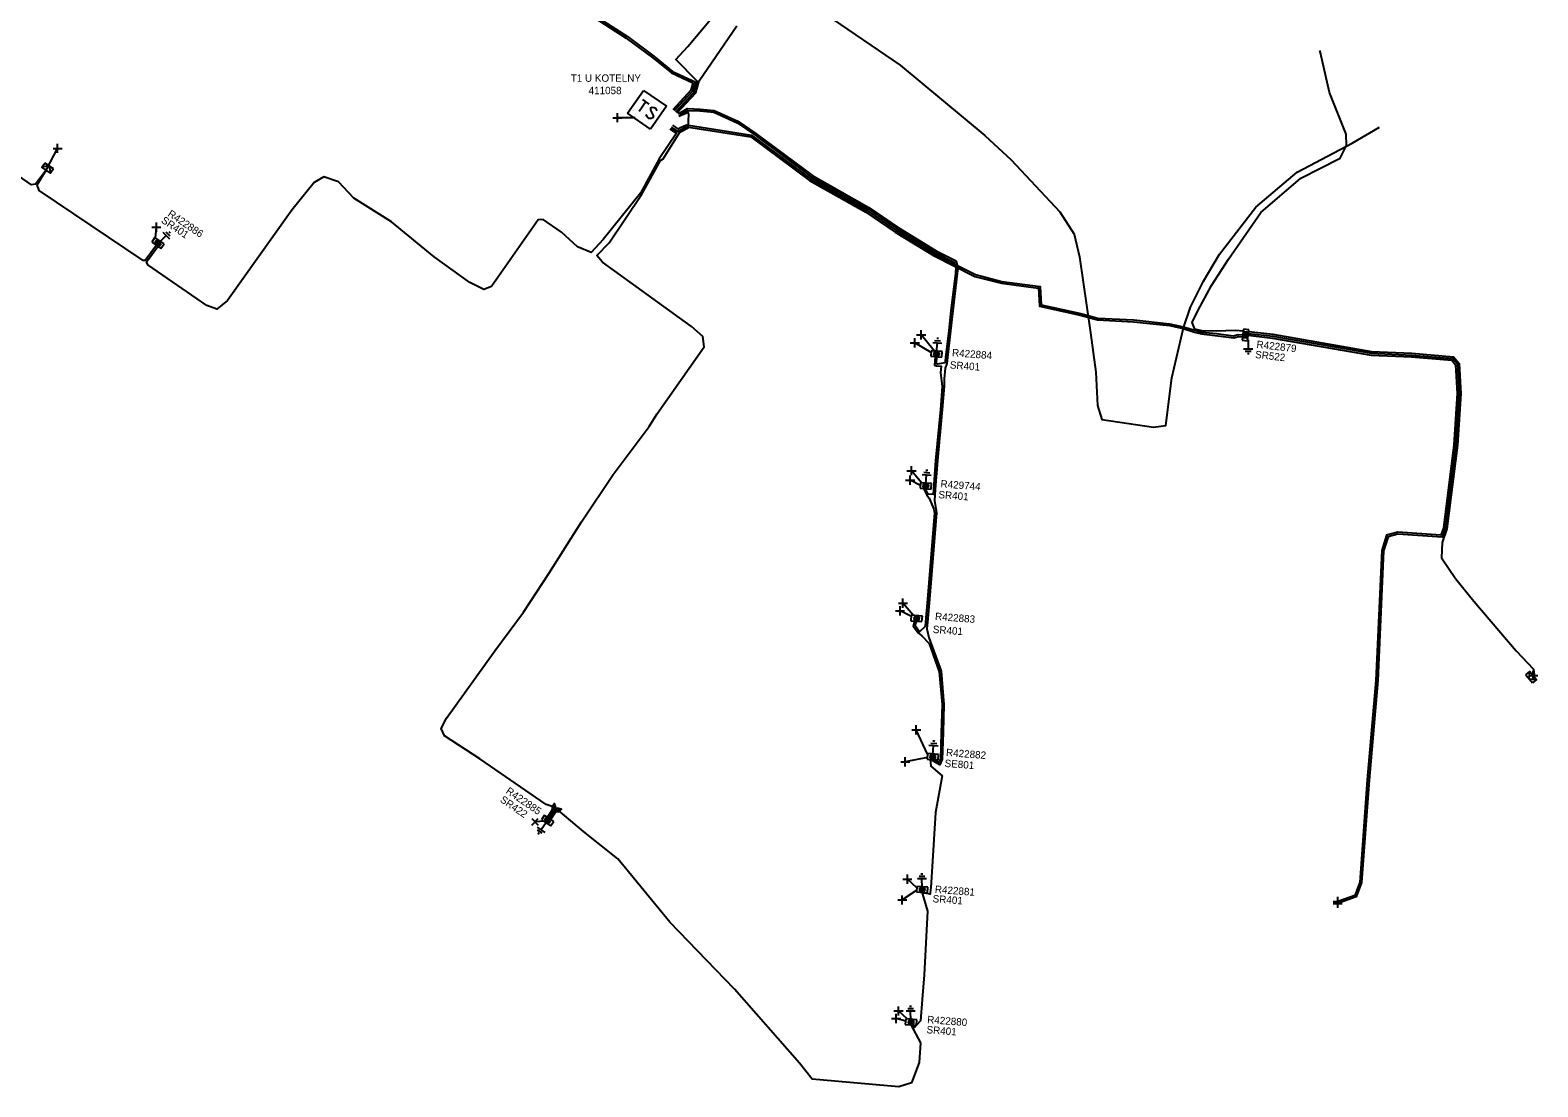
# Model space of a CAD drawing. Extents: x -540247 to -537390, y -1183890 to -1180355.
# Drawn here: x -538895.4 to -538691.2, y -1181583.2 to -1181440.1 of the extents above; entities that cross this region are included whole.
import ezdxf

# ---------------------------------------------------------------- set-up
doc = ezdxf.new("R2010")
doc.units = 0
for name, color, linetype in [('Vrstva 1', 7, 'Continuous'), ('Vrstva 14', 7, 'Continuous'), ('Vrstva 15', 7, 'Continuous'), ('Vrstva 19', 7, 'Continuous'), ('Vrstva 20', 7, 'Continuous'), ('Vrstva 25', 7, 'Continuous'), ('Vrstva 26', 7, 'Continuous'), ('Vrstva 27', 7, 'Continuous'), ('Vrstva 28', 7, 'Continuous'), ('Vrstva 29', 7, 'Continuous'), ('Vrstva 30', 7, 'Continuous'), ('Vrstva 31', 7, 'Continuous'), ('Vrstva 34', 7, 'Continuous'), ('Vrstva 4', 7, 'Continuous'), ('Vrstva 5', 7, 'Continuous'), ('Vrstva 52', 7, 'Continuous'), ('Vrstva 59', 7, 'Continuous'), ('Vrstva 6', 7, 'Continuous'), ('Vrstva 8', 7, 'Continuous'), ('Vrstva 9', 7, 'Continuous')]:
    doc.layers.add(name, color=color, linetype=linetype)

# ---------------------------------------------------------------- blocks, each defined once
blk = doc.blocks.new('NN870')
at = {"layer": 'Vrstva 4'}
for points in [[(0, -0.25), (0.5, 0), (0, 0.25), (-0.5, 0), (0, -0.25)], [(0.37, 0), (0, 0.19), (-0.36, 0), (0, -0.19), (0.37, 0)], [(0.24, 0), (0, 0.12), (-0.25, 0), (0, -0.12), (0.24, 0)], [(0.12, 0), (0, 0.06), (-0.13, 0), (0, -0.06), (0.12, 0)]]:
    blk.add_lwpolyline(points, dxfattribs=at)
blk = doc.blocks.new('NN800')
at = {"layer": 'Vrstva 1'}
for points in [[(-0.44, 0.44), (0.44, -0.44)], [(-0.44, -0.44), (0.44, 0.44)]]:
    blk.add_lwpolyline(points, dxfattribs=at)
blk = doc.blocks.new('NN620')
at = {"layer": 'Vrstva 8'}
for points in [[(0.75, 0), (-0.75, 0)], [(-0.75, 0), (-0.75, -0.75)], [(0.75, -0.75), (0.75, 0)], [(-0.75, -0.75), (0.75, -0.75)], [(0.37, -0.18), (-0.38, -0.18)], [(-0.38, -0.18), (-0.38, -0.56)], [(-0.38, -0.56), (0.37, -0.56)], [(0.32, -0.23), (-0.33, -0.23)], [(-0.33, -0.23), (-0.33, -0.51)], [(-0.33, -0.51), (0.32, -0.51)], [(0.27, -0.27), (-0.28, -0.27)], [(-0.28, -0.27), (-0.28, -0.46)], [(-0.28, -0.46), (0.27, -0.46)], [(0.23, -0.32), (-0.23, -0.32)], [(-0.23, -0.32), (-0.23, -0.42)], [(-0.23, -0.42), (0.23, -0.42)], [(-0.19, -0.37), (0.19, -0.37)], [(0.23, -0.42), (0.23, -0.32)], [(0.27, -0.46), (0.27, -0.27)], [(0.32, -0.51), (0.32, -0.23)], [(0.37, -0.56), (0.37, -0.18)]]:
    blk.add_lwpolyline(points, dxfattribs=at)
blk = doc.blocks.new('NN630')
at = {"layer": 'Vrstva 9'}
for points in [[(0, -0.7), (-0.7, 0)], [(-0.7, -0.7), (-0.7, 0), (0.7, 0), (0.7, -0.7)], [(-0.7, -0.7), (0.7, -0.7)], [(0, -0.7), (0.7, 0)]]:
    blk.add_lwpolyline(points, dxfattribs=at)
blk = doc.blocks.new('NN810')
at = {"layer": 'Vrstva 14'}
for points in [[(0.63, -1.89), (-0.62, -1.89)], [(0, -0.64), (0, -1.89)], [(0.39, -2.2), (-0.4, -2.2)], [(0, -2.52), (-0.12, -2.52)], [(0.14, -2.52), (0, -2.52)]]:
    blk.add_lwpolyline(points, dxfattribs=at)
blk = doc.blocks.new('NN640')
at = {"layer": 'Vrstva 6'}
for points in [[(-1.89, 1.89), (1.89, 1.89)], [(-1.89, -1.89), (-1.89, 1.89)], [(-1.26, 0.79), (-0.22, 0.79)], [(-0.73, 0.79), (-0.73, -0.79)], [(1.2, 0.66), (0.94, 0.79), (0.66, 0.79), (0.41, 0.66), (0.28, 0.47), (0.28, 0.41), (0.41, 0.22), (1.13, -0.16), (1.26, -0.32), (1.26, -0.47), (1.13, -0.66), (0.91, -0.79), (0.63, -0.79), (0.5, -0.73), (0.28, -0.6)], [(1.89, 1.89), (1.89, -1.89)], [(1.89, -1.89), (-1.89, -1.89)]]:
    blk.add_lwpolyline(points, dxfattribs=at)

msp = doc.modelspace()

# ---------------------------------------------------------------- linework, layer by layer
at = {"layer": 'Vrstva 20'}
for points in [[(-538825.39, -1181546.69), (-538824.78, -1181545.73), (-538824.28, -1181546.05), (-538824.89, -1181547.01)], [(-538824.73, -1181545.87), (-538824.67, -1181545.32), (-538824.27, -1181545.36), (-538824.33, -1181545.91)], [(-538824.58, -1181545.7), (-538823.98, -1181545.54), (-538823.88, -1181545.92), (-538824.48, -1181546.08)]]:
    msp.add_lwpolyline(points, close=True, dxfattribs=at)
at = {"layer": 'Vrstva 5'}
for points in [[(-538807.98, -1181451.14), (-538805.49, -1181448.44), (-538805.07, -1181446.97), (-538807.96, -1181444.03), (-538806.36, -1181442.28), (-538803.07, -1181438.32), (-538800.84, -1181435.28), (-538797.72, -1181430.79), (-538794.12, -1181424.69), (-538791.28, -1181420.03), (-538789.66, -1181417.6), (-538789.3, -1181416.42), (-538790.35, -1181415.15), (-538797.73, -1181410.23), (-538799.81, -1181408.71), (-538799.06, -1181407.05), (-538797.2, -1181404.36), (-538793.47, -1181398.28), (-538786.22, -1181388.48), (-538784.54, -1181389.82), (-538778.6, -1181393.59), (-538776.61, -1181394.98)], [(-538888.29, -1181392.57), (-538887.52, -1181392.55), (-538886.24, -1181392.24), (-538884.34, -1181393.09), (-538875.36, -1181399.76), (-538871.83, -1181401.51), (-538870.75, -1181402.54), (-538866.63, -1181405.56), (-538861.42, -1181409.32), (-538857.16, -1181411.59), (-538856.57, -1181412.23), (-538845.58, -1181419.91), (-538842.35, -1181421.71), (-538841.45, -1181422.89), (-538836.12, -1181426.5), (-538830.84, -1181430.24), (-538827.39, -1181432.21), (-538823.29, -1181435.26), (-538814.54, -1181440.92), (-538810.94, -1181443.6), (-538808.43, -1181445.64), (-538805.35, -1181447.04), (-538805.71, -1181448.31), (-538808.19, -1181451)], [(-538828.9, -1181433.68), (-538827.34, -1181433.06), (-538826.94, -1181433.71), (-538824.16, -1181434.99), (-538814.68, -1181441.12), (-538811.1, -1181443.8), (-538808.55, -1181445.86), (-538805.65, -1181447.19), (-538805.94, -1181448.19), (-538808.39, -1181450.85)], [(-538787.64, -1181437.92), (-538777.57, -1181444.8), (-538766.1, -1181454.31), (-538762.56, -1181457.61), (-538755.94, -1181464.69), (-538754, -1181467.68), (-538753.29, -1181470.78), (-538751.78, -1181481.08), (-538751.06, -1181486.39), (-538750.84, -1181490.9), (-538750.25, -1181492.83), (-538743.27, -1181493.84), (-538741.58, -1181493.63), (-538740.8, -1181487.17), (-538739.22, -1181480.38), (-538738.23, -1181477.57), (-538736.5, -1181474.08), (-538734.34, -1181470.43), (-538729.42, -1181464.06), (-538723.78, -1181459.31), (-538716.34, -1181455.38), (-538712.63, -1181453.2)], [(-538807.8, -1181451.26), (-538805.26, -1181448.56), (-538804.79, -1181446.9), (-538799.71, -1181439.45)], [(-538731.1, -1181480.85), (-538732.14, -1181480.76), (-538734.77, -1181480.86), (-538736.7, -1181480.81), (-538737.65, -1181480.55), (-538738.02, -1181479.68), (-538737.25, -1181478.11), (-538735.41, -1181474.65), (-538733.12, -1181471.08), (-538728.73, -1181464.75), (-538723.3, -1181460.09), (-538717.99, -1181457.42), (-538717.1, -1181455.7), (-538717.16, -1181454.17), (-538719.42, -1181448.49), (-538720.64, -1181443.15), (-538720.72, -1181442.8)], [(-538878.34, -1181469.21), (-538879.88, -1181471.28), (-538880.11, -1181471.25), (-538894.24, -1181461.79), (-538894.47, -1181461.03), (-538893.25, -1181459.04), (-538893.26, -1181459.03), (-538894.71, -1181460.92), (-538895.25, -1181461.02), (-538907.2, -1181452.8), (-538908.8, -1181450.11), (-538907.86, -1181449.08)], [(-538824.47, -1181545.34), (-538825.53, -1181544.96), (-538834.52, -1181538.81), (-538839.29, -1181535.69), (-538839.75, -1181534.69), (-538839.06, -1181533.28), (-538832.5, -1181524.15), (-538828.63, -1181518.94), (-538825.18, -1181513.66), (-538820.76, -1181506.7), (-538816.44, -1181500.27), (-538811.57, -1181493.77), (-538810.53, -1181492.08), (-538804.15, -1181482.97), (-538804.3, -1181481.55), (-538805.84, -1181480.19), (-538817.92, -1181471.49), (-538818.67, -1181470.58), (-538817.02, -1181468.89), (-538812.57, -1181462.29), (-538810.06, -1181457.74), (-538809.67, -1181457.51), (-538807.45, -1181453.9), (-538806.28, -1181453.31), (-538806.2, -1181451.46), (-538806.28, -1181451.2), (-538807.58, -1181451.74)], [(-538807.59, -1181451.41), (-538806.41, -1181450.66), (-538804.68, -1181450.77), (-538802.76, -1181450.95), (-538799.58, -1181452.4), (-538797.13, -1181454.06), (-538789.46, -1181459.77), (-538781.83, -1181464.07), (-538777.85, -1181466.78), (-538772.69, -1181469.97), (-538769.98, -1181471.32), (-538769.78, -1181472.2), (-538769.86, -1181473.02), (-538770.46, -1181478.07), (-538770.76, -1181480.78), (-538771.18, -1181484.43), (-538771.27, -1181485.21), (-538771.47, -1181485.86), (-538771.64, -1181487.31), (-538771.63, -1181488.3), (-538771.89, -1181491.47), (-538772.54, -1181498.37), (-538772.82, -1181502.29), (-538772.92, -1181503.8), (-538772.66, -1181505.46), (-538773.58, -1181516.62), (-538773.88, -1181520.26), (-538773.95, -1181521.17), (-538773.68, -1181522.34), (-538772.05, -1181526.93), (-538771.65, -1181531.44), (-538771.77, -1181535.23), (-538771.9, -1181538.88), (-538771.94, -1181538.99), (-538772.2, -1181539.6), (-538773.2, -1181539.03), (-538773.2, -1181538.88)], [(-538807.43, -1181451.52), (-538806.35, -1181450.92), (-538804.7, -1181451.01), (-538802.82, -1181451.19), (-538799.68, -1181452.62), (-538797.27, -1181454.26), (-538789.59, -1181459.98), (-538781.96, -1181464.28), (-538777.98, -1181466.99), (-538772.82, -1181470.18), (-538770.26, -1181471.48), (-538770.02, -1181472.18), (-538770.1, -1181473), (-538770.7, -1181478.05), (-538771.01, -1181480.76), (-538771.43, -1181484.41), (-538771.48, -1181484.88), (-538771.51, -1181485.13), (-538772.52, -1181485.3), (-538772.65, -1181485.26), (-538772.61, -1181484.32)], [(-538808.77, -1181453.43), (-538807.89, -1181454.02), (-538810.21, -1181457.49), (-538812.78, -1181462.16), (-538817.8, -1181468.44), (-538819.42, -1181470.2), (-538821.31, -1181469.4), (-538823.45, -1181467.42), (-538825.95, -1181465.73), (-538826.63, -1181465.74), (-538832.95, -1181474.78), (-538834, -1181475.19), (-538835.89, -1181474.25), (-538840.69, -1181470.75), (-538846.51, -1181466.01), (-538851.6, -1181462.8), (-538853.68, -1181460.63), (-538855.65, -1181459.95), (-538856.98, -1181460.72), (-538859.98, -1181464.45), (-538868.72, -1181476.71), (-538870.15, -1181477.84), (-538871.52, -1181477.37), (-538879.51, -1181471.85), (-538879.68, -1181471.43), (-538878.14, -1181469.36)], [(-538808.6, -1181453.19), (-538807.69, -1181453.79), (-538807.62, -1181453.71), (-538806.51, -1181453.14), (-538797.82, -1181454.53), (-538789.86, -1181460.41), (-538782.23, -1181464.71), (-538778.25, -1181467.41), (-538773.07, -1181470.61), (-538767.48, -1181473.44), (-538763.85, -1181474.33), (-538758.84, -1181475.03), (-538758.7, -1181477.46), (-538753.19, -1181478.69), (-538750.86, -1181479.3), (-538745.96, -1181479.57), (-538741.11, -1181480.09), (-538739.24, -1181480.49), (-538737.7, -1181480.97), (-538736.76, -1181481.19), (-538734.89, -1181481.41), (-538732.4, -1181481.76), (-538731.77, -1181481.57), (-538731.19, -1181481.59)], [(-538808.44, -1181452.94), (-538807.64, -1181453.47), (-538807.34, -1181453.25), (-538806.55, -1181452.88), (-538797.71, -1181454.3), (-538789.73, -1181460.2), (-538782.1, -1181464.5), (-538778.12, -1181467.2), (-538772.94, -1181470.4), (-538767.38, -1181473.17), (-538763.81, -1181474.1), (-538758.6, -1181474.81), (-538758.46, -1181477.26), (-538753.13, -1181478.45), (-538750.82, -1181479.06), (-538745.94, -1181479.32), (-538741.09, -1181479.85), (-538739.18, -1181480.25), (-538737.67, -1181480.71), (-538736.73, -1181480.97), (-538734.75, -1181481.15), (-538732.45, -1181481.49), (-538731.78, -1181481.29), (-538731.16, -1181481.33)], [(-538772.85, -1181484.3), (-538772.91, -1181485.44), (-538772.64, -1181485.53), (-538772.02, -1181485.6), (-538772.12, -1181486.45), (-538771.89, -1181488.32), (-538772.14, -1181491.45), (-538772.79, -1181498.35), (-538773.07, -1181502.27), (-538773.11, -1181502.98), (-538773.77, -1181502.95), (-538774.14, -1181502.19)], [(-538774.43, -1181502.16), (-538773.99, -1181503.06), (-538773.67, -1181503.49), (-538773, -1181504.97), (-538772.91, -1181505.46), (-538773.83, -1181516.61), (-538774.13, -1181520.24), (-538774.19, -1181520.88), (-538774.96, -1181521.57), (-538775.55, -1181520.78), (-538775.38, -1181520.14)], [(-538775.63, -1181520.12), (-538775.83, -1181520.82), (-538775.15, -1181521.74), (-538774.64, -1181522.11), (-538773.66, -1181523.17), (-538772.29, -1181526.99), (-538771.9, -1181531.44), (-538772.02, -1181535.21), (-538772.14, -1181538.82), (-538772.2, -1181538.96), (-538772.34, -1181539.23), (-538772.84, -1181538.91)], [(-538773.51, -1181538.86), (-538773.44, -1181539.77), (-538771.88, -1181541.11), (-538772.79, -1181546.08), (-538773.26, -1181553.36), (-538773.44, -1181556.24), (-538773.51, -1181556.97), (-538773.53, -1181557.15), (-538774.33, -1181556.99), (-538774.35, -1181556.91)], [(-538825.22, -1181546.8), (-538824.51, -1181545.67), (-538824.47, -1181545.34)], [(-538823.93, -1181545.73), (-538824.39, -1181545.85), (-538825.06, -1181546.9)], [(-538776.14, -1181574.83), (-538774.85, -1181577.27), (-538775.02, -1181579.96), (-538776.05, -1181582.71), (-538777.78, -1181583.24), (-538789.51, -1181582.18), (-538791.22, -1181580.01), (-538800.04, -1181570.01), (-538808.77, -1181560.92), (-538815.81, -1181552.34), (-538820.5, -1181548.65), (-538823.93, -1181545.73)], [(-538774.62, -1181556.89), (-538774.54, -1181557.14), (-538773.89, -1181559.43), (-538774.31, -1181568.07), (-538774.6, -1181571.39), (-538774.85, -1181574.3), (-538775.38, -1181574.89), (-538775.65, -1181575.19), (-538775.83, -1181574.85)]]:
    msp.add_lwpolyline(points, dxfattribs=at)
at = {"layer": 'Vrstva 52'}
for points in [[(-538730.37, -1181480.9), (-538727.08, -1181481.27), (-538713.72, -1181483.59), (-538708.27, -1181483.84), (-538702.61, -1181484.3), (-538701.85, -1181485.21), (-538701.62, -1181489.28), (-538702.07, -1181496.27), (-538703.51, -1181507.62), (-538704.17, -1181509.48), (-538704.26, -1181511.56), (-538702.34, -1181514.34), (-538699.86, -1181517.43), (-538694.14, -1181524.17), (-538691.79, -1181526.66), (-538691.69, -1181527.37), (-538691.82, -1181527.49)], [(-538730.43, -1181481.39), (-538727.16, -1181481.77), (-538713.78, -1181484.09), (-538708.31, -1181484.34), (-538702.86, -1181484.78), (-538702.34, -1181485.41), (-538702.12, -1181489.28), (-538702.57, -1181496.23), (-538703.99, -1181507.5), (-538704.33, -1181508.49), (-538710.17, -1181508.07), (-538711.68, -1181508.49), (-538712.34, -1181510.56), (-538713.14, -1181528.16), (-538714.3, -1181541.66), (-538715.32, -1181555.51), (-538716, -1181557.29), (-538718.29, -1181558.11)], [(-538730.4, -1181481.14), (-538727.12, -1181481.52), (-538713.75, -1181483.84), (-538708.29, -1181484.09), (-538702.74, -1181484.54), (-538702.1, -1181485.31), (-538701.87, -1181489.28), (-538702.32, -1181496.25), (-538703.75, -1181507.56), (-538704.17, -1181508.76), (-538710.15, -1181508.33), (-538711.48, -1181508.69), (-538712.1, -1181510.6), (-538712.89, -1181528.18), (-538714.05, -1181541.68), (-538715.08, -1181555.57), (-538715.8, -1181557.49), (-538718.31, -1181558.38)]]:
    msp.add_lwpolyline(points, dxfattribs=at)
at = {"layer": 'Vrstva 59'}
for points in [[(-538813.48, -1181451.92), (-538815.89, -1181451.92)], [(-538893.26, -1181459.03), (-538891.72, -1181456.07)], [(-538878.45, -1181468.25), (-538878.34, -1181466.75)], [(-538773.39, -1181483.74), (-538775.59, -1181482.43)], [(-538772.95, -1181483.55), (-538774.75, -1181481.34)], [(-538774.84, -1181501.77), (-538776.23, -1181501.04)], [(-538774.67, -1181501.42), (-538776.04, -1181499.75)], [(-538776.06, -1181519.49), (-538777.6, -1181518.74)], [(-538775.76, -1181519.39), (-538777.2, -1181517.71)], [(-538773.84, -1181538.25), (-538775.4, -1181534.86)], [(-538773.9, -1181538.63), (-538776.89, -1181539.19)], [(-538825.78, -1181547.24), (-538827.05, -1181547.33)], [(-538775.31, -1181556.26), (-538776.61, -1181555.09)], [(-538775.32, -1181556.58), (-538777.29, -1181557.92)], [(-538776.82, -1181574.34), (-538778.12, -1181573.98)], [(-538776.6, -1181574.07), (-538777.8, -1181572.96)]]:
    msp.add_lwpolyline(points, dxfattribs=at)

# ---------------------------------------------------------------- block references
at = {"layer": 'Vrstva 15'}
for p, rotation in [((-538878.34, -1181469.21), 135), ((-538772.69, -1181484.31), 175.64315828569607), ((-538774.14, -1181502.18), 175.64315828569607), ((-538773.2, -1181538.88), 175.64315842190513), ((-538825.14, -1181546.85), -34.37234147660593), ((-538774.62, -1181556.89), -179.80129164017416), ((-538776.14, -1181574.83), -179.35714153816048)]:
    msp.add_blockref('NN810', p, dxfattribs=dict(at, rotation=rotation))
msp.add_blockref('NN810', (-538730.43, -1181481.39), dxfattribs=at)
at = {"layer": 'Vrstva 19'}
for p, rotation in [((-538824.47, -1181545.34), 82.73377747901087), ((-538823.93, -1181545.73), 14.067502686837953)]:
    msp.add_blockref('NN870', p, dxfattribs=dict(at, rotation=rotation))
at = {"layer": 'Vrstva 25', "rotation": -34.64668053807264}
msp.add_blockref('NN640', (-538811.88, -1181450.84), dxfattribs=at)
at = {"layer": 'Vrstva 28'}
for p, rotation in [((-538878.34, -1181469.21), 145.91936665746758), ((-538730.43, -1181481.39), -96.41697496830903), ((-538772.69, -1181484.31), 175.65466110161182), ((-538774.14, -1181502.18), 175.65466110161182), ((-538775.38, -1181520.14), 175.65466110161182), ((-538773.2, -1181538.88), 175.6546611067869), ((-538825.14, -1181546.85), -34.49882221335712), ((-538774.62, -1181556.89), 175.65466123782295), ((-538776.14, -1181574.83), 175.654661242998)]:
    msp.add_blockref('NN620', p, dxfattribs=dict(at, rotation=rotation))
at = {"layer": 'Vrstva 31'}
for p, rotation in [((-538893.26, -1181459.03), 145.64415565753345), ((-538691.82, -1181527.49), -49.908330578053)]:
    msp.add_blockref('NN630', p, dxfattribs=dict(at, rotation=rotation))
at = {"layer": 'Vrstva 34'}
for p, rotation in [((-538815.89, -1181451.92), 44.99999995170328), ((-538891.72, -1181456.07), 45), ((-538878.34, -1181466.75), 45), ((-538774.75, -1181481.34), 45), ((-538775.59, -1181482.43), 45), ((-538776.04, -1181499.75), 45), ((-538776.23, -1181501.04), 45), ((-538777.2, -1181517.71), 44.99999995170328), ((-538777.6, -1181518.74), 45), ((-538691.82, -1181527.49), 45.00000009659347), ((-538775.4, -1181534.86), 45), ((-538776.89, -1181539.19), 45), ((-538776.61, -1181555.09), 45), ((-538777.29, -1181557.92), 45), ((-538718.31, -1181558.38), 45), ((-538718.29, -1181558.11), 44.99999995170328), ((-538777.8, -1181572.96), 45), ((-538778.12, -1181573.98), 45)]:
    msp.add_blockref('NN800', p, dxfattribs=dict(at, rotation=rotation))
msp.add_blockref('NN800', (-538827.05, -1181547.33), dxfattribs=at)

# ---------------------------------------------------------------- texts
at = {"layer": 'Vrstva 26'}
msp.add_text('411058', height=1, dxfattribs=at).set_placement((-538819.79, -1181448.73))
at = {"layer": 'Vrstva 27'}
msp.add_text('T1 U KOTELNY', height=1, dxfattribs=at).set_placement((-538822.21, -1181447.05))
at = {"layer": 'Vrstva 29'}
for s, rotation, p in [('R422886', 325.919, (-538876.9, -1181465.17)), ('R422879', 353.583, (-538729.35, -1181483.1)), ('R422884', 355.655, (-538770.59, -1181484.23)), ('R429744', 355.655, (-538772.14, -1181502.01)), ('R422883', 355.655, (-538772.89, -1181519.97)), ('R422882', 355.655, (-538771.4, -1181538.41)), ('R422885', 325.501, (-538831.1, -1181543.37)), ('R422881', 355.655, (-538772.91, -1181556.95)), ('R422880', 355.655, (-538773.95, -1181574.6))]:
    msp.add_text(s, height=1, rotation=rotation, dxfattribs=at).set_placement(p)
at = {"layer": 'Vrstva 30'}
for s, rotation, p in [('SR401', 325.919, (-538877.78, -1181466.05)), ('SR401', 355.655, (-538770.88, -1181485.89)), ('SR522', 353.583, (-538729.54, -1181484.47)), ('SR401', 355.655, (-538772.43, -1181503.47)), ('SR401', 355.655, (-538773.19, -1181521.73)), ('SE801', 355.655, (-538771.59, -1181539.88)), ('SR422', 325.501, (-538831.88, -1181544.54)), ('SR401', 355.655, (-538773.21, -1181558.22)), ('SR401', 355.655, (-538774.04, -1181575.97))]:
    msp.add_text(s, height=1, rotation=rotation, dxfattribs=at).set_placement(p)

doc.saveas('drawing.dxf')
